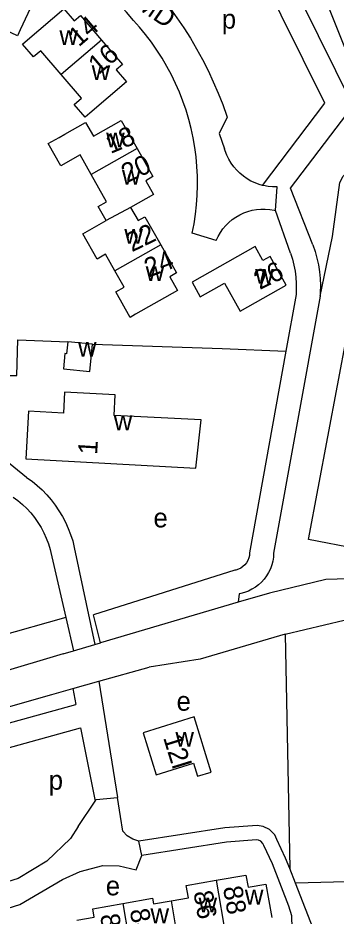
# Model space of a CAD drawing. Extents: x 162883 to 165538, y 383986 to 385172.
# Drawn here: x 164543.6 to 164609.9, y 384557.3 to 384744.4 of the extents above; entities that cross this region are included whole.
import ezdxf

# ---------------------------------------------------------------- set-up
doc = ezdxf.new("R2010")
doc.units = 0
for name, color, linetype in [('BLT_Basislijn', 7, 'Continuous'), ('BLT_Bebouwing', 7, 'Continuous'), ('BLT_Centroide', 7, 'Continuous'), ('BLT_Hoogspanningsmast_en_leidingen', 7, 'Continuous'), ('BLT_Huisnummer', 7, 'Continuous'), ('BLT_Huisnummer_ tussenligend', 7, 'Continuous'), ('BLT_Onderverdeling_panden', 7, 'Continuous'), ('BLT_Straatnaam_verkleind', 7, 'Continuous')]:
    doc.layers.add(name, color=color, linetype=linetype)

msp = doc.modelspace()

# ---------------------------------------------------------------- linework, layer by layer
at = {"layer": 'BLT_Basislijn'}
for p, q in [((164597.28, 384704.25), (164597.58, 384709.18)), ((164605.06, 384697.09), (164600.4, 384708.91)), ((164600.36, 384695.39), (164597.28, 384704.25)), ((164584.93, 384698.04), (164579.93, 384699.55)), ((164604.12, 384635.73), (164614.8, 384692.63)), ((164606.53, 384686.39), (164596.87, 384632.9)), ((164601.54, 384686.76), (164599.42, 384674.98)), ((164559.15, 384676.41), (164586.12, 384675.55)), ((164586.12, 384675.55), (164599.42, 384674.98)), ((164599.42, 384674.98), (164591.87, 384632.97)), ((164545.44, 384648.68), (164535.12, 384656.94)), ((164624.39, 384631.85), (164604.12, 384635.73)), ((164555.37, 384634.09), (164559.65, 384613.89)), ((164550.49, 384633.01), (164553.59, 384619.51)), ((164588.79, 384629.33), (164559.38, 384620.05)), ((164596.02, 384624.57), (164589.49, 384622.66)), ((164589.71, 384624.41), (164589.49, 384622.66)), ((164589.49, 384622.66), (164560.81, 384614.24)), ((164553.59, 384619.51), (164428.29, 384583.78)), ((164553.59, 384619.51), (164555.18, 384612.55)), ((164560.81, 384614.24), (164559.38, 384620.05)), ((164599.24, 384616.01), (164581.59, 384610.81)), ((164555.18, 384612.55), (164559.65, 384613.89)), ((164559.65, 384613.89), (164560.81, 384614.24)), ((164553.06, 384611.91), (164434.29, 384576.61)), ((164553.06, 384611.91), (164555.18, 384612.55)), ((164581.59, 384610.81), (164570.97, 384609.13)), ((164560.5, 384606.2), (164570.97, 384609.13)), ((164555.04, 384604.67), (164560.5, 384606.2)), ((164560.5, 384606.2), (164564.35, 384581.98)), ((164555.04, 384604.67), (164555.69, 384601.4)), ((164439.44, 384569.26), (164555.69, 384601.4)), ((164533, 384589.94), (164556.66, 384596.48)), ((164556.66, 384596.48), (164559.7, 384581.2)), ((164556.18, 384575.94), (164559.7, 384581.2)), ((164569.42, 384569.95), (164568.82, 384572.9))]:
    msp.add_line(p, q, dxfattribs=at)
for points in [[(164606.53, 384686.39), (164609.12, 384698.86), (164610.62, 384710.09), (164611.33, 384711.45), (164612.53, 384712.53), (164631.05, 384720.07), (164599.22, 384772.76), (164586.06, 384776.57), (164579.97, 384788.91)], [(164600.4, 384708.91), (164613.39, 384726.04), (164591.69, 384770.05), (164577.13, 384777.39)], [(164567.7, 384743.82), (164566.22, 384745.56), (164564.68, 384747.24), (164563.09, 384748.86), (164561.43, 384750.43), (164559.73, 384751.94), (164557.97, 384753.39), (164556.16, 384754.78), (164554.3, 384756.1), (164552.4, 384757.36), (164550.46, 384758.55), (164548.47, 384759.67), (164546.45, 384760.71), (164544.39, 384761.69), (164542.3, 384762.6), (164540.18, 384763.43), (164538.03, 384764.18), (164535.85, 384764.86), (164533.65, 384765.47), (164531.43, 384765.99), (164529.2, 384766.44), (164528.5, 384766.56)], [(164594.58, 384709.5), (164607.54, 384726.6), (164593.95, 384754.15)], [(164570.35, 384752.43), (164572.03, 384750.51), (164573.66, 384748.53), (164575.23, 384746.5), (164576.73, 384744.43), (164578.16, 384742.31), (164579.53, 384740.15), (164580.83, 384737.94), (164582.06, 384735.7), (164583.22, 384733.41), (164584.31, 384731.1), (164585.32, 384728.74), (164586.26, 384726.36), (164587.13, 384723.95), (164587.2, 384723.74)], [(164579.93, 384699.55), (164580.31, 384701.51), (164580.6, 384703.49), (164580.82, 384705.47), (164580.96, 384707.46), (164581.02, 384709.45), (164581, 384711.45), (164580.9, 384713.44), (164580.72, 384715.43), (164580.46, 384717.4), (164580.12, 384719.37), (164579.71, 384721.32), (164579.21, 384723.25), (164578.64, 384725.16), (164577.99, 384727.05), (164577.27, 384728.91), (164576.47, 384730.74), (164575.6, 384732.53), (164574.66, 384734.29), (164573.65, 384736.01), (164572.57, 384737.69), (164571.42, 384739.32), (164570.21, 384740.91), (164568.94, 384742.44), (164567.7, 384743.82)], [(164587.2, 384723.74), (164585.5, 384720.33), (164586.64, 384717.11)], [(164594.58, 384709.5), (164593.88, 384709.69), (164593, 384710.02), (164592.15, 384710.41), (164591.33, 384710.88), (164590.56, 384711.41), (164589.84, 384712.01), (164589.17, 384712.67), (164588.55, 384713.38), (164588.01, 384714.14), (164587.52, 384714.95), (164587.11, 384715.79), (164586.77, 384716.67), (164586.64, 384717.11)], [(164597.58, 384709.18), (164596.64, 384709.19), (164595.71, 384709.28), (164594.78, 384709.45), (164594.58, 384709.5)], [(164584.93, 384698.04), (164585.32, 384698.87), (164585.79, 384699.67), (164586.31, 384700.42), (164586.9, 384701.13), (164587.55, 384701.78), (164588.26, 384702.37), (164589.01, 384702.9), (164589.81, 384703.36), (164590.64, 384703.75), (164591.5, 384704.07), (164592.39, 384704.31), (164593.3, 384704.47), (164594.21, 384704.56), (164595.13, 384704.56), (164596.05, 384704.48), (164596.96, 384704.33), (164597.28, 384704.25)], [(164600.36, 384695.39), (164600.76, 384694.16), (164601.08, 384692.91), (164601.33, 384691.64), (164601.49, 384690.36), (164601.58, 384689.07), (164601.59, 384687.78), (164601.54, 384686.76)], [(164605.06, 384697.09), (164605.51, 384695.72), (164605.88, 384694.33), (164606.18, 384692.92), (164606.4, 384691.5), (164606.54, 384690.07), (164606.6, 384688.63), (164606.57, 384687.2), (164606.53, 384686.39)], [(164521.22, 384668.14), (164525.08, 384669.9), (164543.44, 384669.93), (164543.63, 384677.35), (164554, 384676.9)], [(164545.44, 384648.68), (164546.57, 384647.87), (164547.64, 384646.99), (164548.67, 384646.05), (164549.64, 384645.05), (164550.54, 384644), (164551.39, 384642.89), (164552.17, 384641.74), (164552.89, 384640.55), (164553.53, 384639.32), (164554.11, 384638.05), (164554.6, 384636.76), (164555.03, 384635.43), (164555.37, 384634.09)], [(164542.62, 384644.56), (164543.62, 384643.83), (164544.57, 384643.03), (164545.47, 384642.18), (164546.31, 384641.27), (164547.09, 384640.3), (164547.8, 384639.29), (164548.45, 384638.24), (164549.03, 384637.15), (164549.54, 384636.02), (164549.97, 384634.86), (164550.33, 384633.67), (164550.49, 384633.01)], [(164591.87, 384632.97), (164591.82, 384632.42), (164591.69, 384631.89), (164591.49, 384631.38), (164591.21, 384630.91), (164590.88, 384630.48), (164590.48, 384630.1), (164590.02, 384629.79), (164589.54, 384629.55), (164589.01, 384629.38), (164588.79, 384629.33)], [(164596.87, 384632.9), (164596.82, 384632.06), (164596.68, 384631.24), (164596.47, 384630.43), (164596.19, 384629.64), (164595.83, 384628.88), (164595.4, 384628.17), (164594.9, 384627.49), (164594.34, 384626.87), (164593.73, 384626.3), (164593.06, 384625.8), (164592.35, 384625.36), (164591.6, 384624.99), (164590.81, 384624.69), (164590.01, 384624.47), (164589.71, 384624.41)], [(164619.43, 384627.73), (164607.72, 384627.43), (164596.02, 384624.57)], [(164599.24, 384616.01), (164611.55, 384618.96), (164616.54, 384619.31), (164621.95, 384619.16), (164629.99, 384618.05), (164650.69, 384614.27)], [(164599.24, 384616.01), (164600.21, 384567.19)], [(164442.92, 384572.76), (164550.7, 384603.45), (164555.04, 384604.67)], [(164559.7, 384581.2), (164559.94, 384581.56), (164564.35, 384581.98)], [(164568.82, 384572.9), (164567.53, 384573.33), (164566.37, 384574), (164565.46, 384574.96), (164564.96, 384578.02), (164564.35, 384581.98)], [(164556.18, 384575.94), (164554.59, 384573.48), (164549.66, 384568.74), (164543.71, 384565.14), (164540.17, 384564.04)], [(164600.21, 384567.19), (164599.36, 384569.37), (164597.55, 384573.25), (164597.1, 384574.19), (164596, 384575.33), (164594.68, 384575.99), (164593.41, 384576.2), (164586.68, 384575.67), (164568.82, 384572.9)], [(164596.69, 384545.66), (164598.65, 384546.43), (164600.76, 384552.19), (164600.65, 384557.32), (164600.04, 384559.39), (164596.6, 384568.19), (164594.84, 384571.97), (164594.6, 384572.45), (164594.19, 384572.88), (164593.74, 384573.11), (164593.29, 384573.18), (164587.03, 384572.69), (164569.42, 384569.95)], [(164515.11, 384556.74), (164516.15, 384556.71), (164530.41, 384556.48), (164536.46, 384557.35), (164544, 384559.73), (164552.89, 384564.9), (164556.58, 384566.59), (164561.28, 384567.83), (164564.73, 384567.77), (164568.27, 384566.96), (164569.42, 384569.95)], [(164601.4, 384564.14), (164600.21, 384567.19)], [(164648.95, 384565.38), (164601.4, 384564.14)], [(164608.15, 384546.89), (164601.4, 384564.14)]]:
    msp.add_lwpolyline(points, dxfattribs=at)
at = {"layer": 'BLT_Bebouwing'}
for p, q in [((164567.09, 384704.92), (164562.01, 384702.18)), ((164559.15, 384676.41), (164554, 384676.9)), ((164545.28, 384652.52), (164580.65, 384650.62))]:
    msp.add_line(p, q, dxfattribs=at)
for points in [[(164539.94, 384756.66), (164546.01, 384753.84), (164544.23, 384750), (164545.33, 384752.36), (164548.33, 384750.96), (164544.11, 384741.88), (164543.54, 384740.65), (164539.39, 384742.58), (164534.44, 384744.89), (164535.3, 384746.69)], [(164552.62, 384732.6), (164548.38, 384737.55), (164546.86, 384736.25), (164544.59, 384738.91), (164545.61, 384739.79), (164553.21, 384746.28), (164555.36, 384743.77), (164556.64, 384744.87), (164561.01, 384739.77)], [(164561.01, 384739.77), (164565.37, 384734.66), (164564.08, 384733.56), (164566.22, 384731.05), (164558.63, 384724.56), (164557.6, 384723.68), (164555.33, 384726.35), (164556.85, 384727.65), (164552.62, 384732.6)], [(164558.87, 384711.77), (164556.56, 384715.85), (164552.54, 384713.58), (164549.93, 384718.21), (164552.2, 384719.5), (164553.38, 384720.16), (164557.73, 384722.62), (164559.36, 384719.74), (164565.15, 384723.01), (164568.44, 384717.17)], [(164568.44, 384717.17), (164571.74, 384711.33), (164570.23, 384710.48), (164571.86, 384707.61), (164567.09, 384704.92)], [(164562.01, 384702.18), (164560.34, 384705.12), (164562.07, 384706.1), (164558.87, 384711.77)], [(164567.09, 384704.92), (164568.65, 384702.16), (164570.08, 384702.96), (164573.37, 384697.11)], [(164563.8, 384691.71), (164561.87, 384695.14), (164560.13, 384694.15), (164557.15, 384699.44), (164562.01, 384702.18)], [(164573.37, 384697.11), (164576.66, 384691.26), (164575.23, 384690.45), (164576.85, 384687.57), (164568.14, 384682.67), (164566.97, 384682.01), (164563.99, 384687.3), (164565.73, 384688.28), (164563.8, 384691.71)], [(164599.49, 384688.74), (164596.12, 384694.71), (164594.65, 384693.88), (164593.03, 384696.76), (164579.88, 384689.35), (164581.59, 384686.31), (164586.62, 384689.14), (164589.89, 384683.33), (164599.49, 384688.74)], [(164554, 384676.9), (164553.76, 384674.42), (164553.43, 384674.45), (164553.13, 384671.26), (164558.6, 384670.74), (164559.15, 384676.41)], [(164580.65, 384650.62), (164581.8, 384660.63), (164563.64, 384661.58), (164563.87, 384665.85), (164553.36, 384666.41), (164553.12, 384662.07), (164545.82, 384662.47), (164545.28, 384652.52)], [(164572.42, 384586.72), (164580.19, 384589.13), (164581.03, 384586.42), (164583.89, 384587.3), (164580.35, 384598.77), (164569.71, 384595.45), (164572.42, 384586.72)], [(164575.5, 384560.48), (164579.12, 384561.12), (164578.67, 384563.67), (164584.88, 384564.75)], [(164584.88, 384564.75), (164591.1, 384565.84), (164591.54, 384563.29), (164595.24, 384563.94), (164596.46, 384556.98)], [(164565.44, 384559.91), (164571.67, 384561), (164571.87, 384559.85), (164575.5, 384560.48)], [(164555.92, 384556.45), (164559.52, 384557.06), (164559.21, 384558.82), (164565.44, 384559.91)]]:
    msp.add_lwpolyline(points, dxfattribs=at)
at = {"layer": 'BLT_Hoogspanningsmast_en_leidingen'}
msp.add_line((164618.02, 384722.18), (164596.83, 384775.62), dxfattribs=at)
at = {"layer": 'BLT_Onderverdeling_panden'}
for p, q in [((164561.01, 384739.77), (164552.62, 384732.6)), ((164568.44, 384717.17), (164558.87, 384711.77)), ((164573.37, 384697.11), (164563.8, 384691.71)), ((164584.88, 384564.75), (164586.96, 384552.91)), ((164565.44, 384559.91), (164567.17, 384550.01)), ((164575.5, 384560.48), (164577.03, 384551.73))]:
    msp.add_line(p, q, dxfattribs=at)

# ---------------------------------------------------------------- texts
at = {"layer": 'BLT_Centroide'}
for s, p in [('p', (164586.08, 384742.15)), ('w', (164552.27, 384738.75)), ('w', (164558.98, 384731.45)), ('w', (164562, 384717.41)), ('w', (164565.3, 384709.66)), ('w', (164565.79, 384697.34)), ('w', (164570.23, 384689.59)), ('w', (164593.01, 384689.03)), ('w', (164556.14, 384673.83)), ('w', (164563.58, 384658.5)), ('e', (164571.85, 384638.26)), ('e', (164576.66, 384600.07)), ('w', (164576.42, 384592.59)), ('p', (164550.05, 384583.62)), ('e', (164561.93, 384561.61)), ('w', (164590.88, 384559.7)), ('w', (164581.22, 384558.08)), ('w', (164571.23, 384555.81))]:
    msp.add_text(s, height=4, dxfattribs=at).set_placement(p)
at = {"layer": 'BLT_Huisnummer'}
for s, rotation, p in [('14', 40.505, (164556.29, 384738.22)), ('16', 40.505, (164560.41, 384732.43)), ('18', 22.5944, (164562.9, 384716.02)), ('20', 25.0392, (164566.32, 384709.94)), ('22', 25.8084, (164567.35, 384695.54)), ('24', 21.2583, (164570.88, 384690.26)), ('26', 25.9817, (164593.97, 384687.69)), ('1', 86.435, (164560.11, 384653.34)), ('12l', 287.2576, (164573.83, 384594.48)), ('88', 279.9027, (164586.31, 384563.25)), ('82', 279.9079, (164560.71, 384557.47))]:
    msp.add_text(s, height=4, rotation=rotation, dxfattribs=at).set_placement(p)
at = {"layer": 'BLT_Huisnummer_ tussenligend'}
for s, p in [('86', (164580.16, 384562.28)), ('84', (164566.9, 384558.55))]:
    msp.add_text(s, height=4, rotation=279.9079, dxfattribs=at).set_placement(p)
at = {"layer": 'BLT_Straatnaam_verkleind'}
msp.add_text('KROMMENBEEMD', height=4, rotation=325.6789, dxfattribs=at).set_placement((164535.9, 384768.54))

doc.saveas('drawing.dxf')
